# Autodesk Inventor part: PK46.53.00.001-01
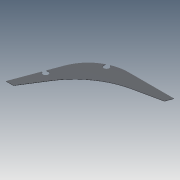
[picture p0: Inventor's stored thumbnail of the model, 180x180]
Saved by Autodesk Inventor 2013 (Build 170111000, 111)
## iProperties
Created: 2005-03
Part Number: PK46.53.00.001-01
Material: Steel, Mild
Document SubType Name: Modeling
Designer: HKostja
Manufacturer: Standard
Standards Organization: Custom
Density: 7.86 g/cm^3
Mass: 4751.84 g
Surface Area: 3132.04 cm^2
Volume: 604.56 cm^3
Author: HKostja
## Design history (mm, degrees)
sketch "Эскиз1"
  geometry: L1 (264.331, 0)-(690, 0); L2 (690, 0)-(665.652, -65.629); L3 (-170, -646.916)-(-240, -646.916); L4 (-240, -646.916)-(-91.941, -247.826); L5 (-170, -646.916)-(-32.608, -429.61); L6 (414.127, -118.858)-(665.652, -65.629); L7 (0, 0)-(559.054, -803.691); L8 (-148.869, -401.272)-(-144.181, -403.012); L9 (-137.737, -371.269)-(-133.05, -373.008); L10 (89.677, -42.515)-(91.976, -46.956); L11 (119.608, -28.638)-(121.512, -33.261); L12 (89.677, -42.515)-(104.341, -34.926); L13 (119.608, -28.638)-(104.341, -34.926); L14 (103.508, -35.71)-(103.28, -35.269); L15 (-143.908, -386.046)-(-143.303, -386.271); A1 r 380 centre (264.331, -380) between (264.331, 0) and (-91.941, -247.826); A2 r 25.5 centre (-120, -394.916) between (-144.181, -403.012) and (-133.05, -373.008); A3 r 25.5 centre (115, -57.916) between (91.976, -46.956) and (121.512, -33.261); A4 r 700 centre (559.054, -803.691) between (414.127, -118.858) and (-32.608, -429.61); 1 further point
  constraints: 30 end point, 13 point on circle, 11 point on line, 6 tangent, 5 parallel, 4 centre point, 4 equal length, 3 perpendicular, 1 coincident, 1 equal radius, 1 horizontal, 1 other
  dimensions: "d0" = 690 distance of L7.start L1.end; "d1" = 70 distance of L3.start L3.end; "d3" = 240 horizontal distance of L7.start L3.end; "d6" = 380 radius of A1; "d9" = 252 distance from line of A2.centre L3; "d10" = 120 horizontal distance of A2.centre L3.end; "d11" = 51 diameter of A2; "d12" = 589 distance from line of A3.centre L3; "d13" = 355 horizontal distance of A3.centre L3.end; "d15" = 700 radius of A4; "d16" = 180 distance from line of L1 point (125.21, -180); "d17" = 5 distance of L10.start L10.end; "d18" = 5 distance of L11.start L11.end (= d17); "d22" = 0.49637 distance of L14.start L14.end (derived); "d23" = 0.64509 distance of L15.start L15.end (derived)
extrude "Выдавливание1" new body sketch "Эскиз1" distance "d7" = 4; taper "d8" = 0 deg
body "Solid1"
